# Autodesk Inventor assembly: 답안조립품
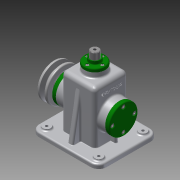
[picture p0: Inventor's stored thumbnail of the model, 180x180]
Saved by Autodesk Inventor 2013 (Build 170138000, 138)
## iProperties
Created: 2016-01
Part Number: 답안조립품
Document SubType Name: Assembly
Designer: Administrator
Author: Administrator
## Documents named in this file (19)
- C:\Users\Administrator\Desktop\460127V1004\답안조립품.iam
- C:\Users\Administrator\Desktop\460127V1004\1. 본체.ipt
- C:\Users\Administrator\Desktop\460127V1004\V-벨트풀리.ipt
- C:\Users\Administrator\Desktop\460127V1004\고정핀.ipt
- C:\Users\Administrator\Desktop\460127V1004\뒤커버.ipt
- C:\Users\Administrator\Desktop\460127V1004\링크.ipt
- C:\Users\Administrator\Desktop\460127V1004\멈춤링 6 x 5.ipt
- C:\Users\Administrator\Desktop\460127V1004\멈춤링 15 x 1.ipt
- C:\Users\Administrator\Desktop\460127V1004\베어링 15 x 35 x 11.ipt
- C:\Users\Administrator\Desktop\460127V1004\볼트 M3 x 8.ipt
- C:\Users\Administrator\Desktop\460127V1004\볼트 M4 x 10.ipt
- C:\Users\Administrator\Desktop\460127V1004\볼트 M6 x 12.ipt
- C:\Users\Administrator\Desktop\460127V1004\상부부시.ipt
- C:\Users\Administrator\Desktop\460127V1004\슬라이드바.ipt
- C:\Users\Administrator\Desktop\460127V1004\앞커버.ipt
- C:\Users\Administrator\Desktop\460127V1004\오일실 15 25 7.ipt
- C:\Users\Administrator\Desktop\460127V1004\와셔.ipt
- C:\Users\Administrator\Desktop\460127V1004\키 5 x 5 x 14.ipt
- C:\Users\Administrator\Desktop\460127V1004\편심축.ipt
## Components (16 placed, 6 different names)
1. 1. 본체:1
2. V-벨트풀리:1 — 각도:2
3. 고정핀:1
4. ISO 4018 M6 x 12:1
5. ISO 4762 M4 x 10:1
6. ISO 4762 M4 x 10:3
7. ISO 4762 M4 x 10:4
8. ISO 4762 M4 x 10:5
9. ISO 4762 M4 x 10:2
10. ISO 4762 M4 x 10:6
11. ISO 4762 M4 x 10:7
12. ISO 4762 M4 x 10:8
13. ISO 4762 M3 x 8:1
14. ISO 4762 M3 x 8:2
15. ISO 4762 M3 x 8:3
16. ISO 4762 M3 x 8:4
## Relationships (1: Angle 1)
- 각도:2 [Angle]: V-벨트풀리:1
